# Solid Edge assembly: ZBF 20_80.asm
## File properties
Title: Zylinder
Author: bmolnar
Template: iso metric assembly.asm
Last saved by: bmolnar
Revision: 18
Application: Solid Edge
Username: bmolnar
Dokumentum tartalom típus: 1
Document Number: ZBF 20/80
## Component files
Profilrohr.par
Kolbenstange.par
Kit.par
Mutter.par
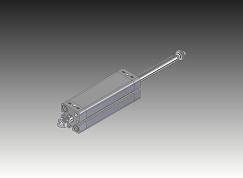
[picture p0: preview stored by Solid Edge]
